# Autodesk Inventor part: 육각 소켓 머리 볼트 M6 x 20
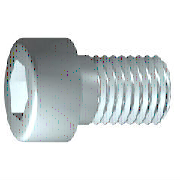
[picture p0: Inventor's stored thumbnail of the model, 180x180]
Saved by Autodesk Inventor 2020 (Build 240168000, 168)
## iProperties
Created: 2012-02
Part Number: 육각 소켓 머리 볼트 M6 x 20
Material: 강철, 연강
Description: 6각 소켓 머리 캡 나사
Document SubType Name: Modeling
Standard: ISO 4762
Designer: mdu-01
Standard Revision: Fourth edition 2004-03-01
Standards Organization: ISO
Language: ko-KR
Size Designation: M6 x 20
Categories: <MemberInstance><Categories><Category DisplayName="조임쇠" InternalName="e4da775c-781d-43d5-af7c-5136215cf5a6" Mnemonic="FSTN"><Category DisplayName="볼트" InternalN
Density: 7.75 g/cm^3
Appearance: 강철
IsCustomPart: 1
Author: mdu-01
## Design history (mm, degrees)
sketch "스케치1"
  geometry: L1 (-1.333, 0)-(20, 0); L2 (20, 0)-(20, 3); L3 (20, 3)-(2.5, 3); L4 (2.5, 3)-(1.886, 3); L5 (1.886, 3)-(0, 3); L6 (0, 3)-(0, 5); L7 (0, 5)-(-6, 5); L8 (-6, 5)-(-6, 2.887); L9 (-6, 2.887)-(-3, 2.887); L10 (-3, 2.887)-(-1.333, 0); L11 (-11.2, 0)-(25.2, 0) reference; L12 (0, -1)-(0, 6) reference; L13 (2.5, 3)-(0, 3)
  constraints: 22 end point, 6 parallel, 2 collinear, 2 perpendicular, 1 horizontal, 1 point on line
  dimensions: "d1" = 17.5 distance from line of L3.end L2 (= GEL); "d2" = 0.61355 distance of L4.end L3.end (computed from GAL); "d3" = 6 distance between parallel lines of L8 L6 (= KOH); "d4" = 3 distance of L8.end L9.end (= INTI); "d5" = 60 deg angle of L10 L1; "d6" = 6 diameter of L3 L1 (= GD); "d7" = 6 diameter of L5 L1 (= BDM); "d8" = 5.7735 diameter of L9 L1 (= 1.1547 x SW); "d9" = 10 diameter of L7 L1 (= KOD); "d26" = 20 distance between parallel lines of L12 L2 (= NLG)
revolve "본체" sketch "스케치1" stored, may be unused: angle "d10" = 90 deg
sketch "스케치2"
  geometry: L1 (0, -7)-(0, 7) reference; L2 (-7, 0)-(7, 0) reference; L3 (2.887, 0)-(1.443, -2.5); L4 (1.443, -2.5)-(-1.443, -2.5); L5 (-1.443, -2.5)-(-2.887, 0); L6 (-2.887, 0)-(-1.443, 2.5); L7 (-1.443, 2.5)-(1.443, 2.5); L8 (1.443, 2.5)-(2.887, 0); 2 further points
  constraints: 12 end point, 1 coincident, 1 horizontal alignment, 1 point on line, 12 other
extrude "슬롯" join sketch "스케치2" stored distance "d11" = 10; taper "d12" = 0 deg
workplane "Work Plane1"
fillet "Fillet2" dims "d30" = 0.1 (= R)
body "Solid1"
fillet "모깎기1" dims "d17" = 0.6 (= RR)
feature "스레드" dims "d13" = 17.5 (= GEL), "d14" = 0
chamfer "모따기1" distance "d15" = 0.61345 (= -0.5 x SPD + 0.5 x GD); stored, may be unused: second distance "d16" = 0.61345 (= GUL), angle "d27" = 45 deg
other parameters: "GD" = 6 [user parameter; used in 2 equation terms], "NLG" = 20 [user parameter; used in 1 equation term], "GEL" = 17.5 [user parameter; used in 2 equation terms], "KOD" = 10 [user parameter; used in 1 equation term], "KOH" = 6 [user parameter; used in 1 equation term], "INTI" = 3 [user parameter; used in 1 equation term], "GAL" = 0.61345 (= 0.61345 x PTC) [user parameter; used in 1 equation term], "GUL" = 0.61345 (= 0.61345 x PTC) [user parameter; used in 1 equation term], "BDM" = 6 (= NND) [user parameter; used in 1 equation term], "SW" = 5 [user parameter; used in 2 equation terms], "RR" = 0.6 [user parameter; used in 1 equation term], "SPD" = 4.7731 (= NND - 1.2269 x PTC) [user parameter; used in 1 equation term], "d19" = 0, "d28" = 0, "d29" = 0, "R" = 0.1 [user parameter; used in 1 equation term], "TOA" = 30 deg [user parameter], "GD1" = 4.7731 (= THREADDIA - 1.2269 x PTC) [user parameter], "THREADDIA" = 6 [user parameter; used in 1 equation term], "FAWI" = 45 deg [user parameter], "PTC" = 1 [user parameter; used in 5 equation terms], "NND" = 6 [user parameter; used in 2 equation terms], "E0" = 5.775 (= 1.155 x SW) [user parameter]
